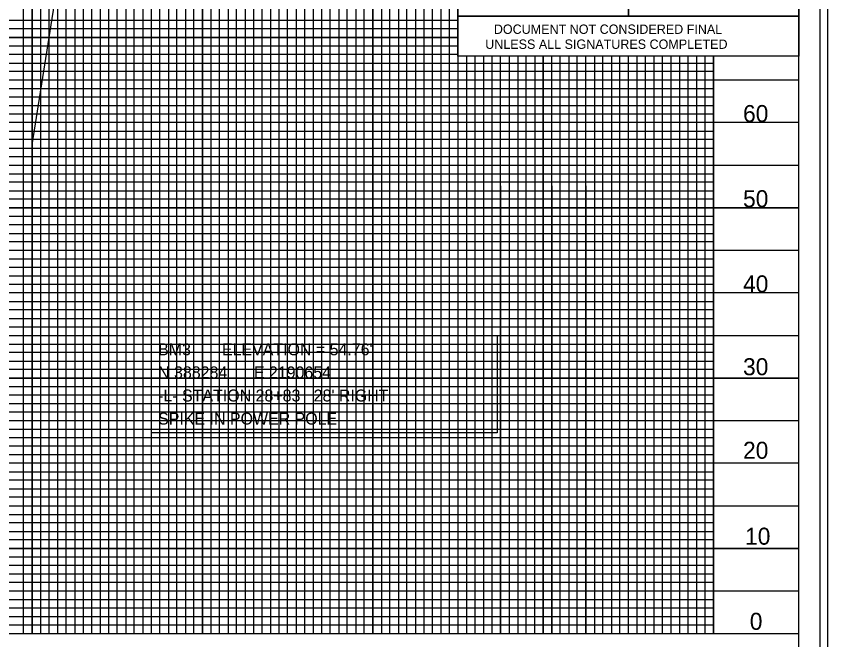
# Model space of a CAD drawing. Extents: x 1019474 to 1021161, y 504129 to 505324.
# Drawn here: x 1020681.9 to 1021158.2, y 504700.7 to 505066.8 of the extents above; entities that cross this region are included whole.
import ezdxf

# ---------------------------------------------------------------- set-up
doc = ezdxf.new("R2010")
doc.units = 0
for name, color, linetype in [('Exist Vertical Profile Vertical Axis Label', 7, 'Continuous'), ('Prop Grid Mask', 7, 'Continuous'), ('Prop Vertical Profile Grade Label', 7, 'Continuous'), ('Prop VPI Label', 7, 'Continuous'), ('Sheet DOT Grid CELL', 7, 'Continuous'), ('Sheet Layout Profile Border Port 1', 7, 'Continuous'), ('Sheet Plot Border Inside CELL', 7, 'Continuous'), ('Sheet Plot Border Outside CELL', 7, 'Continuous'), ('Sheet Profile CELL', 7, 'Continuous'), ('Sheet Profile Grid Major CELL', 7, 'Continuous'), ('Sheet Profile Grid Middle CELL', 7, 'Continuous'), ('Sheet Profile Grid Minor CELL', 7, 'Continuous'), ('Sheet Sticker Exception Certification CELL', 7, 'Continuous')]:
    doc.layers.add(name, color=color, linetype=linetype)

msp = doc.modelspace()

# ---------------------------------------------------------------- linework, layer by layer
at = {"layer": 'Prop Grid Mask'}
msp.add_lwpolyline([(1020761.25, 504879.26), (1020964.1, 504879.26), (1020964.1, 504822.08), (1020761.25, 504822.08)], close=True, dxfattribs=at)
at = {"layer": 'Prop Vertical Profile Grade Label'}
msp.add_line((1020691.22, 504991.16), (1020710.07, 505110.82), dxfattribs=at)
at = {"layer": 'Sheet DOT Grid CELL'}
for p, q in [((1020691.22, 504704.29), (1020691.22, 505204.29)), ((1020741.22, 504704.29), (1020741.22, 505204.29)), ((1020791.22, 504704.29), (1020791.22, 505204.29)), ((1020841.22, 504704.29), (1020841.22, 505204.29)), ((1020891.22, 504704.29), (1020891.22, 505204.29)), ((1020941.22, 504704.29), (1020941.22, 505066.74)), ((1020941.22, 505054.29), (1019641.22, 505054.29)), ((1020991.22, 504704.29), (1020991.22, 505043.24)), ((1021041.22, 504704.29), (1021041.22, 505043.24)), ((1021091.22, 504704.29), (1021091.22, 505043.24)), ((1021141.22, 505004.29), (1019641.22, 505004.29)), ((1021141.22, 504954.29), (1019641.22, 504954.29)), ((1021141.22, 504904.29), (1019641.22, 504904.29)), ((1021141.22, 504854.29), (1019641.22, 504854.29)), ((1021141.22, 504804.29), (1019641.22, 504804.29)), ((1021141.22, 504754.29), (1019641.22, 504754.29))]:
    msp.add_line(p, q, dxfattribs=at)
at = {"layer": 'Sheet Layout Profile Border Port 1'}
msp.add_lwpolyline([(1019691.22, 505043.24), (1019691.22, 504704.29), (1021091.22, 504704.29), (1021091.22, 505043.24)], dxfattribs=at)
at = {"layer": 'Sheet Plot Border Inside CELL'}
msp.add_lwpolyline([(1019487.22, 504151.74), (1021153.72, 504151.74), (1021153.72, 505206.84), (1019487.22, 505206.84)], close=True, dxfattribs=at)
at = {"layer": 'Sheet Plot Border Outside CELL'}
msp.add_lwpolyline([(1019474.22, 504129.29), (1021158.22, 504129.29), (1021158.22, 505229.29), (1019474.22, 505229.29)], close=True, dxfattribs=at)
at = {"layer": 'Sheet Profile CELL'}
msp.add_line((1019641.22, 504704.29), (1021141.22, 504704.29), dxfattribs=at)
for points in [[(1021141.22, 505204.29), (1019641.22, 505204.29), (1019641.22, 504154.29), (1021141.22, 504154.29)], [(1020941.17, 505179.24), (1021041.22, 505179.24), (1021041.22, 505066.74), (1020941.17, 505066.74)], [(1021041.22, 505179.24), (1021141.22, 505179.24), (1021141.22, 505066.74), (1021041.22, 505066.74)]]:
    msp.add_lwpolyline(points, close=True, dxfattribs=at)
at = {"layer": 'Sheet Profile Grid Major CELL'}
for points in [[(1020641.22, 505204.29), (1020691.22, 505204.29), (1020691.22, 504704.29), (1020741.22, 504704.29), (1020741.22, 505204.29), (1020791.22, 505204.29), (1020791.22, 504704.29), (1020841.22, 504704.29), (1020841.22, 505204.29), (1020891.22, 505204.29), (1020891.22, 504704.29), (1020941.22, 504704.29), (1020941.22, 505204.29), (1020967.52, 505204.29)], [(1020941.22, 505104.29), (1019641.22, 505104.29), (1019641.22, 505054.29), (1020941.22, 505054.29)], [(1021091.22, 505043.24), (1021091.22, 504704.29), (1021141.22, 504704.29), (1021141.22, 505054.29)], [(1020991.22, 505043.24), (1020991.22, 504704.29), (1021041.22, 504704.29), (1021041.22, 504704.29), (1021041.22, 505043.24)], [(1021141.22, 505004.29), (1019641.22, 505004.29), (1019641.22, 504954.29), (1021141.22, 504954.29)], [(1021141.22, 504904.29), (1019641.22, 504904.29), (1019641.22, 504854.29), (1021141.22, 504854.29)], [(1021141.22, 504804.29), (1019641.22, 504804.29), (1019641.22, 504804.29), (1019641.22, 504754.29), (1021141.22, 504754.29)]]:
    msp.add_lwpolyline(points, dxfattribs=at)
at = {"layer": 'Sheet Profile Grid Middle CELL'}
for points in [[(1020666.22, 505204.29), (1020716.22, 505204.29), (1020716.22, 504704.29), (1020766.22, 504704.29), (1020766.22, 505204.29), (1020816.22, 505204.29), (1020816.22, 504704.29), (1020866.22, 504704.29), (1020866.22, 505204.29), (1020916.22, 505204.29), (1020916.22, 504704.29), (1020966.22, 504704.29), (1020966.22, 505043.24)], [(1020966.22, 504967.09), (1020966.22, 504704.29), (1021016.22, 504704.29), (1021016.22, 505043.24)], [(1021016.22, 504967.09), (1021016.22, 504704.29), (1021066.22, 504704.29), (1021066.22, 505043.24)], [(1021141.22, 505029.29), (1019641.22, 505029.29), (1019641.22, 504979.29), (1020966.22, 504979.29)], [(1020966.22, 504979.29), (1021141.22, 504979.29)], [(1021141.22, 504929.29), (1019641.22, 504929.29), (1019641.22, 504879.29), (1021141.22, 504879.29)], [(1021141.22, 504829.29), (1019641.22, 504829.29), (1019641.22, 504779.29), (1021141.22, 504779.29)], [(1021141.22, 504729.29), (1019641.22, 504729.29)]]:
    msp.add_lwpolyline(points, dxfattribs=at)
at = {"layer": 'Sheet Profile Grid Minor CELL'}
for p, q in [((1020941.22, 505064.29), (1019691.22, 505064.29)), ((1020941.22, 505059.29), (1019691.22, 505059.29)), ((1019691.22, 505049.29), (1020941.22, 505049.29)), ((1020941.22, 505044.29), (1019691.22, 505044.29)), ((1019691.22, 505039.29), (1021091.22, 505039.29)), ((1021091.22, 505019.29), (1019691.22, 505019.29)), ((1019691.22, 505014.29), (1021091.22, 505014.29)), ((1021091.22, 504994.29), (1019691.22, 504994.29)), ((1019691.22, 504989.29), (1021091.22, 504989.29)), ((1021091.22, 504969.29), (1019691.22, 504969.29)), ((1019691.22, 504964.29), (1021091.22, 504964.29)), ((1021091.22, 504959.29), (1019691.22, 504959.29)), ((1019691.22, 504949.29), (1021091.22, 504949.29)), ((1021091.22, 504944.29), (1019691.22, 504944.29)), ((1019691.22, 504939.29), (1021091.22, 504939.29)), ((1021091.22, 504934.29), (1019691.22, 504934.29)), ((1019691.22, 504924.29), (1021091.22, 504924.29)), ((1021091.22, 504919.29), (1019691.22, 504919.29)), ((1019691.22, 504914.29), (1021091.22, 504914.29)), ((1021091.22, 504909.29), (1019691.22, 504909.29)), ((1019691.22, 504899.29), (1021091.22, 504899.29)), ((1021091.22, 504894.29), (1019691.22, 504894.29)), ((1019691.22, 504889.29), (1021091.22, 504889.29)), ((1021091.22, 504884.29), (1019691.22, 504884.29)), ((1019691.22, 504874.29), (1021091.22, 504874.29)), ((1021091.22, 504869.29), (1019691.22, 504869.29)), ((1019691.22, 504864.29), (1021091.22, 504864.29)), ((1021091.22, 504859.29), (1019691.22, 504859.29)), ((1019691.22, 504849.29), (1021091.22, 504849.29)), ((1021091.22, 504844.29), (1019691.22, 504844.29)), ((1019691.22, 504839.29), (1021091.22, 504839.29)), ((1021091.22, 504834.29), (1019691.22, 504834.29)), ((1019691.22, 504824.29), (1021091.22, 504824.29)), ((1021091.22, 504819.29), (1019691.22, 504819.29)), ((1021091.22, 504814.29), (1019691.22, 504814.29)), ((1021091.22, 504809.29), (1019691.22, 504809.29)), ((1019691.22, 504799.29), (1021091.22, 504799.29)), ((1021091.22, 504794.29), (1019691.22, 504794.29)), ((1019691.22, 504789.29), (1021091.22, 504789.29)), ((1021091.22, 504784.29), (1019691.22, 504784.29)), ((1019691.22, 504774.29), (1021091.22, 504774.29)), ((1021091.22, 504769.29), (1019691.22, 504769.29)), ((1019691.22, 504764.29), (1021091.22, 504764.29)), ((1021091.22, 504759.29), (1019691.22, 504759.29)), ((1019691.22, 504749.29), (1021091.22, 504749.29)), ((1021091.22, 504744.29), (1019691.22, 504744.29)), ((1019691.22, 504739.29), (1021091.22, 504739.29)), ((1021091.22, 504734.29), (1019691.22, 504734.29)), ((1019691.22, 504724.29), (1021091.22, 504724.29)), ((1021091.22, 504719.29), (1019691.22, 504719.29)), ((1019691.22, 504714.29), (1021091.22, 504714.29))]:
    msp.add_line(p, q, dxfattribs=at)
for points in [[(1020681.22, 504704.29), (1020686.22, 504704.29), (1020686.22, 505204.29)], [(1020696.22, 505204.29), (1020696.22, 504704.29), (1020701.22, 504704.29), (1020701.22, 505204.29)], [(1020706.22, 505204.29), (1020706.22, 504704.29), (1020711.22, 504704.29), (1020711.22, 505204.29)], [(1020721.22, 505204.29), (1020721.22, 504704.29), (1020726.22, 504704.29), (1020726.22, 505204.29)], [(1020731.22, 505204.29), (1020731.22, 504704.29), (1020736.22, 504704.29), (1020736.22, 505204.29)], [(1020746.22, 505204.29), (1020746.22, 504704.29), (1020751.22, 504704.29), (1020751.22, 505204.29)], [(1020756.22, 505204.29), (1020756.22, 504704.29), (1020761.22, 504704.29), (1020761.22, 505204.29)], [(1020771.22, 505204.29), (1020771.22, 504704.29), (1020776.22, 504704.29), (1020776.22, 505204.29)], [(1020781.22, 505204.29), (1020781.22, 504704.29), (1020786.22, 504704.29), (1020786.22, 505204.29)], [(1020796.22, 505204.29), (1020796.22, 504704.29), (1020801.22, 504704.29), (1020801.22, 505204.29)], [(1020806.22, 505204.29), (1020806.22, 504704.29), (1020811.22, 504704.29), (1020811.22, 505204.29)], [(1020821.22, 505204.29), (1020821.22, 504704.29), (1020826.22, 504704.29), (1020826.22, 505204.29)], [(1020831.22, 505204.29), (1020831.22, 504704.29)], [(1020831.22, 504704.29), (1020836.22, 504704.29), (1020836.22, 505204.29)], [(1020846.22, 505204.29), (1020846.22, 504704.29), (1020851.22, 504704.29), (1020851.22, 505204.29)], [(1020856.22, 505204.29), (1020856.22, 504704.29), (1020861.22, 504704.29), (1020861.22, 505204.29)], [(1020871.22, 505204.29), (1020871.22, 504704.29), (1020876.22, 504704.29), (1020876.22, 505204.29)], [(1020881.22, 505204.29), (1020881.22, 504704.29), (1020886.22, 504704.29), (1020886.22, 505204.29)], [(1020896.22, 505204.29), (1020896.22, 504704.29), (1020901.22, 504704.29), (1020901.22, 505204.29)], [(1020906.22, 505204.29), (1020906.22, 504704.29), (1020911.22, 504704.29), (1020911.22, 505204.29)], [(1020921.22, 505204.29), (1020921.22, 504704.29), (1020926.22, 504704.29), (1020926.22, 505204.29)], [(1020931.22, 505204.29), (1020931.22, 504704.29), (1020936.22, 504704.29), (1020936.22, 505204.29)], [(1020946.22, 505043.24), (1020946.22, 504704.29), (1020951.22, 504704.29), (1020951.22, 505043.24)], [(1020956.22, 505043.24), (1020956.22, 504704.29), (1020961.22, 504704.29), (1020961.22, 505043.24)], [(1020971.22, 505043.24), (1020971.22, 504704.29), (1020971.22, 504704.29), (1020976.22, 504704.29), (1020981.22, 504704.29), (1020981.22, 505043.24)], [(1020976.22, 505043.24), (1020976.22, 504704.29)], [(1020986.22, 505043.24), (1020986.12, 504704.34), (1020991.12, 504704.34), (1020996.22, 504704.29), (1020996.22, 505043.24)], [(1020996.22, 504967.09), (1020996.22, 504704.29), (1021001.22, 504704.29), (1021001.22, 505043.24)], [(1021006.22, 505043.24), (1021006.22, 504704.29), (1021011.22, 504704.29), (1021011.22, 505043.24)], [(1021021.22, 505043.24), (1021021.22, 504704.29), (1021026.22, 504704.29), (1021026.22, 505043.24)], [(1021031.22, 505043.24), (1021031.22, 504704.29), (1021036.22, 504704.29), (1021036.22, 505043.24)], [(1021046.22, 505043.24), (1021046.22, 504704.29), (1021051.22, 504704.29), (1021051.22, 505043.24)], [(1021056.22, 505043.24), (1021056.22, 504704.29), (1021061.22, 504704.29), (1021061.22, 505043.24)], [(1021071.22, 505043.24), (1021071.22, 504704.29), (1021076.22, 504704.29), (1021076.22, 505043.24)], [(1021081.22, 505043.24), (1021081.22, 504704.29), (1021086.22, 504704.29), (1021086.22, 505043.24)], [(1021091.22, 505034.29), (1019691.22, 505034.29), (1019691.22, 505024.29), (1021091.22, 505024.29)], [(1021091.22, 505009.29), (1019691.22, 505009.29), (1019691.22, 504999.29), (1021091.22, 504999.29)], [(1021091.22, 504984.29), (1019691.22, 504984.29), (1019691.22, 504974.29), (1021091.22, 504974.29)], [(1021091.22, 504709.29), (1019691.22, 504709.29)]]:
    msp.add_lwpolyline(points, dxfattribs=at)
at = {"layer": 'Sheet Sticker Exception Certification CELL'}
for p, q in [((1020941.17, 505043.24), (1020941.17, 505066.74)), ((1020941.17, 505066.74), (1021141.21, 505066.74)), ((1020941.17, 505043.24), (1020941.17, 505066.74)), ((1020941.17, 505066.74), (1021141.21, 505066.74)), ((1021141.21, 505066.73), (1021141.21, 505043.23)), ((1021141.21, 505066.73), (1021141.21, 505043.23)), ((1021141.21, 505043.24), (1020941.17, 505043.24)), ((1021141.21, 505043.24), (1020941.17, 505043.24))]:
    msp.add_line(p, q, dxfattribs=at)

# ---------------------------------------------------------------- texts
at = {"layer": 'Exist Vertical Profile Vertical Axis Label'}
for s, p in [('60', (1021108.49, 505004.61)), ('50', (1021108.49, 504954.61)), ('40', (1021108.49, 504904.61)), ('30', (1021108.49, 504855.98)), ('20', (1021108.49, 504806.92)), ('10', (1021109.69, 504756.47)), ('0', (1021112.45, 504706.48))]:
    msp.add_text(s, height=10, dxfattribs=at).set_placement(p)
at = {"layer": 'Prop VPI Label'}
for s, p in [("BM3       ELEVATION = 54.76'", (1020765.2, 504867.69)), ('N 388284      E 2190654', (1020765.2, 504854.13)), ("-L- STATION 28+83   28' RIGHT", (1020765.2, 504840.57)), ('SPIKE IN POWER POLE', (1020765.2, 504827.01))]:
    msp.add_text(s, height=7, dxfattribs=at).set_placement(p)
at = {"layer": 'Sheet Sticker Exception Certification CELL'}
for s, p in [('DOCUMENT NOT CONSIDERED FINAL', (1020962.24, 505056.4)), ('DOCUMENT NOT CONSIDERED FINAL', (1020962.24, 505056.4)), ('UNLESS ALL SIGNATURES COMPLETED', (1020957.17, 505047.6)), ('UNLESS ALL SIGNATURES COMPLETED', (1020957.17, 505047.6))]:
    msp.add_text(s, height=5.5, dxfattribs=at).set_placement(p)

doc.saveas('drawing.dxf')
